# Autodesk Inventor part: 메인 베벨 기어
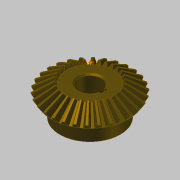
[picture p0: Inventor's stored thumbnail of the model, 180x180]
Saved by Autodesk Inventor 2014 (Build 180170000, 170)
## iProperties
Created: 2016-04
Part Number: 메인 베벨 기어
Material: 강철, 탄소
Document SubType Name: Modeling
Designer: mdu
Categories: <?xml version="1.0" encoding="UTF-16"?> <MemberInstance><Categories><FamilyTemplate><FamilyTemplateParameter ValueType="xs:double" Id="1" ObjectReferenceKey="da
Mass: 269.926 g
Surface Area: 108.837 cm^2
Volume: 34.2981 cm^3
Density: 7.87 g/cm^3
Appearance: 얼룩무늬
CustomPartVersion: 1
Author: mdu
Revision Number: 1
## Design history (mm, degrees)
node "맨 위 점"
node "메쉬 평면2"
sketch "톱니 본체 스케치"
  geometry: L1 (0, 0)-(28.669, -21.997); L2 (28.669, -21.997)-(31.109, -18.336); L3 (31.109, -18.336)-(0, 0); L4 (30, -20)-(0, 0); L5 (17.219, -13.212)-(18.685, -11.013); L6 (28.669, -21.997)-(17.219, -13.212); L7 (31.109, -18.336)-(18.685, -11.013); L8 (0, -39.387)-(0, 6.564) reference; L9 (0, -20)-(31.109, -20)
  constraints: 16 end point, 4 point on line, 3 perpendicular, 2 collinear, 1 horizontal alignment, 1 vertical alignment
  dimensions: "d0" = 60 diameter of L4.start L8 (= da_de); "d1" = 57.33744 diameter of L1.end L8 (= da_dfe); "d2" = 62.2188 diameter of L2.end L8 (= da_dae); "d3" = 14.4 distance between parallel lines of L2 L5 (= da_b); "d4" = 18.3359 vertical distance of L2.end L1.start (= da_ve)
revolve "톱니 본체" sketch "톱니 본체 스케치" stored, may be unused: angle "d5" = 90 deg
node "시작점"
node "톱니 평면"
sketch "시작 스케치"
  geometry: L1 (0, -23.505)-(0, 10.645) reference; L2 (-0.709, -2.928)-(0.709, -2.928); A1 r 19.188 centre (-19.457, -7.014) between (-0.709, -2.928) and (-3.232, 3.229); A2 r 19.188 centre (19.457, -7.014) between (3.232, 3.229) and (0.709, -2.928); A3 r 57.403 centre (0, -54.083) between (3.232, 3.229) and (-3.232, 3.229); 1 further point
  constraints: 6 point on circle, 3 centre point, 3 symmetric about line, 2 end point, 1 coincident, 1 perpendicular, 1 other
  dimensions: "d7" = 19.18795 radius of A1 (= fd_rr); "d8" = 19.45712 horizontal distance of point (0, -54.083) A1.centre (= fd_x); "d9" = 47.06905 vertical distance of point (0, -54.083) A1.centre (= fd_y); "d57" = 57.40327 radius of A3 (= 0.5 x fd_dva + 0.3 x da_he); "d58" = 51.15527 distance from line of A3.centre L2 (= 0.5 x fd_dva - 1.12 x da_he)
node "끝점"
  node "끝 평면"
sketch "3D 스케치 오른쪽"
  node "Helical Curve Right" dims "d65" = 229.90621 (computed from da_dm, da_delta, da_beta), "d66" = 31.5, "d67" = 60 (= da_de), "d68" = -9.82794 (= -da_delta), "d69" = 8.10972 (computed from fd_loft, da_delta)
node "끝 평면 오른쪽"
sketch "끝 스케치 오른쪽"
  geometry: L1 (0, -41.54)-(0, 13.178) reference; L2 (-0.422, -1.69)-(0.422, -1.69); A1 r 11.427 centre (-11.587, -4.123) between (-0.422, -1.69) and (-1.925, 1.977); A2 r 11.427 centre (11.587, -4.123) between (1.925, 1.977) and (0.422, -1.69); A3 r 34.184 centre (0, -32.153) between (1.925, 1.977) and (-1.925, 1.977); 1 further point
  constraints: 6 point on circle, 3 centre point, 3 symmetric about line, 2 end point, 1 coincident, 1 perpendicular, 1 other
  dimensions: "d70" = 11.58699 horizontal distance of A3.centre A1.centre (computed from fd_x, fd_ratio); "d71" = 28.03028 vertical distance of point (0, -32.153) A1.centre (computed from fd_y, fd_ratio); "d72" = 11.4267 radius of A1 (computed from fd_rr, fd_ratio); "d73" = 30.46369 distance from line of point (0, -32.153) L2 (computed from d58, fd_ratio); "d74" = 34.18446 radius of A3 (computed from d57, fd_ratio)
feature "로프트 오른쪽" sketch "끝 스케치 오른쪽" dims "d75" = 0, "d77" = 0, "d79" = 0, "d80" = 90 deg, "d85" = 20, "d92" = 90 deg, "d93" = 90 deg, "da_teethtype" = 0 [user parameter]
sketch "3D 스케치 왼쪽"
  node "Helical Curve Left" dims "d26" = 229.90621 (computed from da_dm, da_delta, da_beta), "d27" = 8.10972 (computed from fd_loft, da_delta), "d28" = 60 (= da_de), "d29" = -9.82794 (= -da_delta)
node "끝 평면 왼쪽"
sketch "끝 스케치 왼쪽" dims "d56" = 10.3728 (derived)
  geometry: L1 (0, -43.753)-(0, 15.405) reference; L2 (-0.422, -1.678)-(0.422, -1.678); A1 r 11.427 centre (-11.587, -4.111) between (-0.422, -1.678) and (-1.925, 1.988); A2 r 11.427 centre (11.587, -4.111) between (1.925, 1.988) and (0.422, -1.678); A3 r 34.184 centre (0, -32.142) between (1.925, 1.988) and (-1.925, 1.988); 2 further points; 1 other entity
  constraints: 6 point on circle, 3 centre point, 3 symmetric about line, 2 end point, 1 coincident, 2 other
  dimensions: "d30" = 11.4267 radius of A1 (computed from fd_rr, fd_ratio); "d31" = 11.58699 horizontal distance of point (0, -32.142) A1.centre (computed from fd_x, fd_ratio); "d32" = 28.03028 vertical distance of A1.centre point (0, -32.142) (computed from fd_y, fd_ratio); "d61" = 34.18446 radius of A3 (computed from d57, fd_ratio); "d62" = 30.46369 distance from line of point (0, -32.142) L2 (computed from d58, fd_ratio)
feature "로프트 왼쪽" sketch "끝 스케치 왼쪽" dims "d35" = 0, "d37" = 0, "d39" = 0, "d40" = 90 deg, "d84" = 10, "d90" = 90 deg, "d91" = 90 deg, "da_teethtype" = 0 [user parameter]
sketch "본체 스케치"
  geometry: L1 (0, -35.038)-(0, -19.531) reference; L2 (28.669, -21.997)-(17.219, -13.212) reference; L3 (17.219, -13.212)-(0, -13.212); L4 (28.669, -21.997)-(0, -21.997)
  constraints: 4 end point, 2 perpendicular, 2 point on line
revolve "본체 고정" sketch "본체 스케치" stored, may be unused: angle "d46" = 90 deg
feature "피치 지름" dims angle "d47" = 90 deg
sketch "스케치8"
  geometry: C1 r 22.5 at (0, 0); 1 further point
  constraints: 1 centre point, 1 coincident
  dimensions: "d94" = 45 diameter of C1
extrude "돌출1" join sketch "스케치8" distance "d95" = 13; taper "d96" = 0 deg
sketch "스케치9"
  geometry: 1 further point
hole "구멍1" sketch "스케치9" at (0, 0) diameter "d97" = 17; stored, may be unused: countersink angle "d101" = 90 deg, drill point angle "d103" = 118 deg; dims "d98" = 6, "d99" = 4, "d100" = 2, "d102" = 8
sketch "스케치10"
  geometry: L1 (8.124, 2.5)-(10.8, 2.5); L2 (10.8, 2.5)-(10.8, -2.5); L3 (10.8, -2.5)-(8.124, -2.5); A1 r 8.5 centre (0, 0) between (8.124, 2.5) and (8.124, -2.5) reference; 1 further point
  constraints: 6 end point, 2 parallel, 2 point on circle, 1 horizontal, 1 perpendicular
  dimensions: "d104" = 5 distance of L1.end L2.end; "d112" = 19.3 dimension on A1 L2
extrude "돌출2" cut sketch "스케치10" stored distance "d106" = 10; taper "d107" = 0 deg
chamfer "모따기1" distance "d108" = 1; stored, may be unused: second distance "d109" = 2, angle "d110" = 45 deg
fillet "모깎기1" dims "d111" = 2
body "Solid1"
feature "로프트" dims "d17" = 0, "d18" = 90 deg, "d19" = 0, "d20" = 90 deg, "d89" = 0, "da_teethtype" = 0 [user parameter]
pattern_circular "원형 패턴" dims angle "d22" = 360 deg, "d88" = 0, "da_teethtype" = 0 [user parameter]
pattern_circular "원형 패턴 오른쪽" dims angle "d82" = 360 deg, "da_teethtype" = 0 [user parameter]
pattern_circular "원형 패턴 왼쪽" dims angle "d42" = 360 deg, "da_teethtype" = 0 [user parameter]
sketch "끝 스케치"
  geometry: L1 (0, -15.359)-(0, 6.983) reference; L2 (-0.422, -1.69)-(0.422, -1.69); A1 r 11.427 centre (-11.587, -4.123) between (-0.422, -1.69) and (-1.925, 1.977); A2 r 11.427 centre (11.587, -4.123) between (1.925, 1.977) and (0.422, -1.69); A3 r 34.184 centre (0, -32.153) between (1.925, 1.977) and (-1.925, 1.977); 1 further point
  constraints: 6 point on circle, 3 centre point, 3 symmetric about line, 2 end point, 1 coincident, 1 other
  dimensions: "d12" = 11.4267 radius of A1 (computed from fd_rr, fd_ratio); "d15" = 11.58699 horizontal distance of A1.centre point (0, -32.153) (computed from fd_x, fd_ratio); "d16" = 28.03028 vertical distance of A1.centre point (0, -32.153) (computed from fd_y, fd_ratio); "d59" = 34.18446 radius of A3 (computed from d57, fd_ratio); "d60" = 30.46369 distance from line of A3.centre L2 (computed from d58, fd_ratio)
sketch "Sketch6"
  geometry: L1 (30, -20)-(0, 0) reference; L2 (0, -37.8)-(0, 6.3) reference
body "Srf1"
other parameters: "da_b" = 14.4 [user parameter; used in 2 equation terms], "da_de" = 60 [user parameter; used in 4 equation terms], "da_dae" = 62.2188 [user parameter; used in 2 equation terms], "da_dfe" = 57.33744 [user parameter; used in 1 equation term], "da_le" = 36.05551 [user parameter; used in 1 equation term], "da_omega" = 90 deg [user parameter; used in 1 equation term], "da_beta" = 0 [user parameter; used in 2 equation terms], "da_delta" = 9.82794 [user parameter; used in 8 equation terms], "da_alpha" = 20 deg [user parameter; used in 2 equation terms], "da_he" = 4.4 [user parameter; used in 4 equation terms], "da_ve" = 18.3359 [user parameter; used in 1 equation term], "fd_dv" = 108.16654 (computed from da_de, da_delta) [user parameter; used in 1 equation term], "fd_dva" = 112.16654 (computed from da_dae, da_delta) [user parameter; used in 3 equation terms], "fd_dvb" = 101.6433 (computed from fd_dv, da_alpha) [user parameter; used in 2 equation terms], "da_zv" = 540.83269 [user parameter; used in 1 equation term], "fd_loft" = 14.62 (= da_b + 0.05 x da_he) [user parameter; used in 4 equation terms], "fd_ratio" = 5.95514 (computed from da_le, fd_loft) [user parameter; used in 15 equation terms], "fd_rr" = 19.18795 (computed from fd_dd, fd_dvb) [user parameter; used in 6 equation terms], "fd_angle" = 0.29367 (computed from da_zv) [user parameter; used in 4 equation terms], "fd_x1" = 1.58802 (computed from da_dvw, fd_angle) [user parameter; used in 1 equation term], "fd_y1" = 54.05995 (computed from da_dvw, fd_angle) [user parameter; used in 1 equation term], "fd_x2" = 17.8691 (computed from fd_rr, fd_angle2, fd_angle) [user parameter; used in 1 equation term], "fd_y2" = 6.9909 (computed from fd_rr, fd_angle2, fd_angle) [user parameter; used in 1 equation term], "fd_x" = 19.45712 (= fd_x1 + fd_x2) [user parameter; used in 4 equation terms], "fd_y" = 47.06905 (= fd_y1 - fd_y2) [user parameter; used in 4 equation terms], "fd_angle2" = 3.43555 (computed from fd_dvb, fd_dd, da_alpha) [user parameter; used in 2 equation terms], "fd_dd" = 108.64654 (= fd_dva - 0.8 x da_he) [user parameter; used in 2 equation terms], "da_dvw" = 108.16654 [user parameter; used in 2 equation terms], "d11" = 14.62 (= fd_loft), "da_dm" = 48.01848 [user parameter; used in 2 equation terms], "da_x" = 0 [user parameter], "da_m" = 2 [user parameter], "d48" = 0, "d49" = 0, "d50" = 90 deg (= da_omega), "d51" = 6 deg (computed from da_z), "d52" = 0, "d53" = 0, "d54" = 0
